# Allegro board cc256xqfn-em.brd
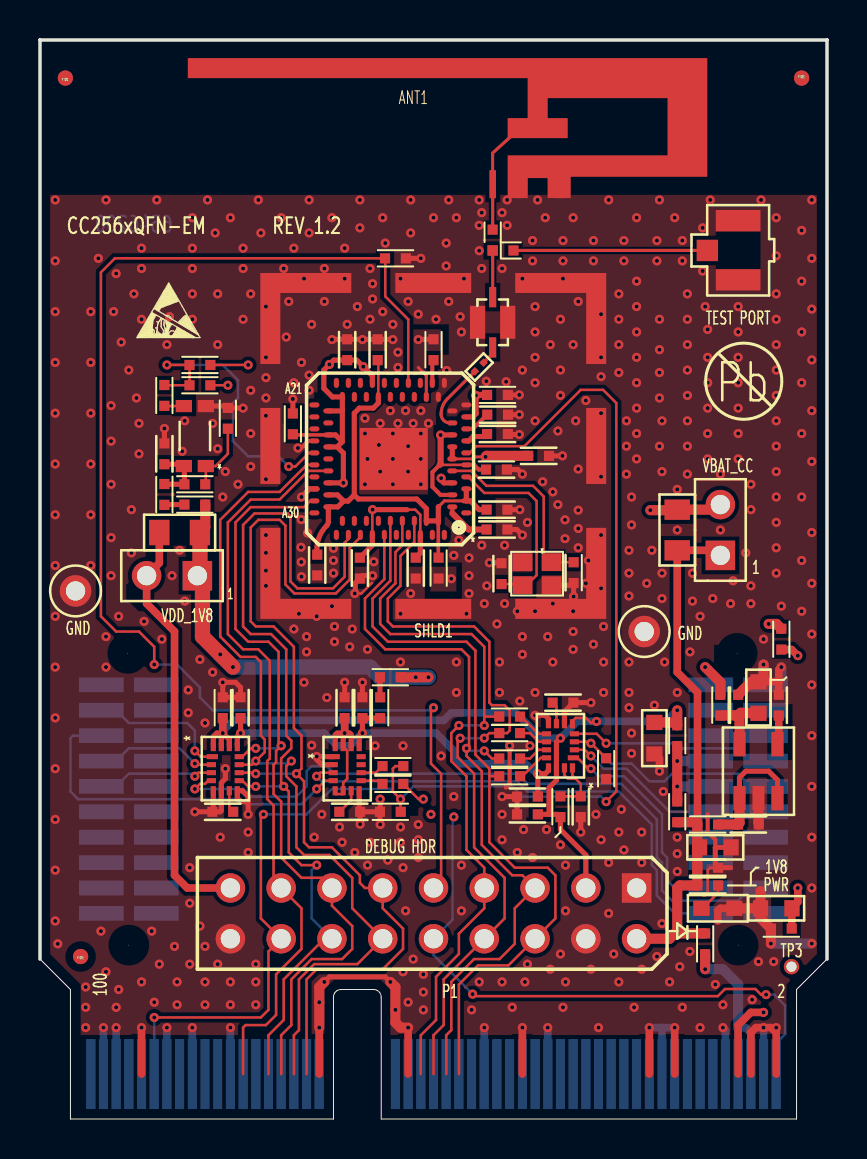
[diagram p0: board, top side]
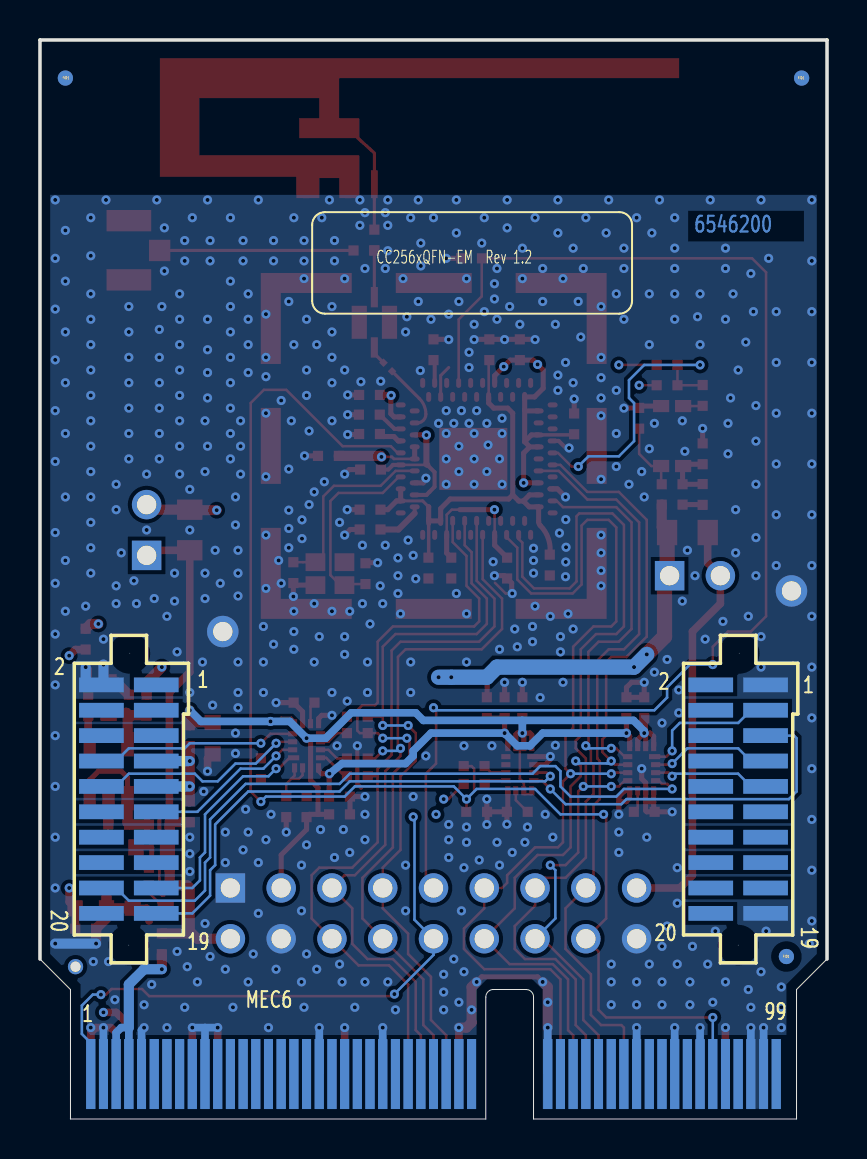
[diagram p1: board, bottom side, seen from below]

Outline 39.37 x 53.98 mm; copper layers: TOP, LYR2_GND, LYR3_PWR, BOTTOM. Coordinates in mm from the lower left corner of the outline.
Outline path: 0,8 0,53.98 39.37,53.98 39.37,8

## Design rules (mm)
nets with their own width: min track width 0.076; nets MLDO_OUT

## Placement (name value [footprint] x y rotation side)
ANT1  N/A  [ANT_IIFA_CC2420_32MIL_MIR]  26.05 46.76 0 top
C1  10uF  [0603]  36.83 10.54 180 top
C2  0.1uF  [0402]  37.08 9.53 180 top
C5  10uF  [0603]  33.78 13.59 0 top
C6  0.1uF  [0402]  33.4 12.57 0 top
C7  1.0uF  [0402]  35.43 14.73 0 top
C8  0.01uF  [0402]  36.96 20.7 90 top
C9  0.1uF  [0402]  34.92 20.7 90 top
C10  10uF  [0603]  35.94 21.08 90 top
C11  0.1uF  [0402]  15.24 20.57 270 top
C12  0.1uF  [0402]  16.13 20.57 90 top
C13  0.1uF  [0402]  9.14 20.57 270 top
C14  0.1uF  [0402]  10.03 20.57 90 top
C15  0.1uF  [0402]  24.38 15.24 0 top
C16  0.1uF  [0402]  24.38 16.13 180 top
C17  0.1uF  [0402]  15.37 38.48 90 top
C18  0.1uF  [0402]  16 27.56 270 top
C19  0.1uF  [0402]  18.8 27.56 270 top
C20  1.0uF  [0402]  22.83 32.49 0 top
C21  1.0uF  [0402]  24.94 33.17 0 top
C22  10pF  [0402]  26.7 27.33 90 top
C23  10pF  [0402]  23.09 27.28 270 top
C24  0.1uF  [0402]  22.86 30.48 0 top
C25  0.47uF  [0402]  16.89 38.48 90 top
C26  0.47uF  [0402]  13.87 27.71 270 top
C27  0.1uF  [0402]  19.68 38.48 90 top
C28  0.1uF  [0402]  22.89 34.26 0 top
C29  0.1uF  [0402]  22.89 35.23 0 top
C30  0.1uF  [0402]  22.86 29.49 0 top
C31  22pF  [0201]  21.97 37.62 45 top
C32  1.0uF  [0402]  22.89 36.22 0 top
C33  0.1uF  [0402]  6.22 33.27 90 top
C34  10uF  [0603]  30.73 19.05 270 top
C35  0.1uF  [0402]  19.94 27.56 270 top
C36  0.1uF  [0402]  12.65 34.77 90 top
D1  GRN  [LED_0603]  33.91 10.54 0 top
FB1  BK1005HS680-T  [FB_0402]  33.4 14.73 0 top
FB2  BK1005HS680-T  [FB_0402]  7.75 30.73 180 top
FB3  BK1005HS680-T  [FB_0402]  17.53 22.1 180 top
FID1  -  [unnamed#2]  38.1 52.07 90 top
FID1#2  -  [unnamed#2]  1.27 52.07 90 top
FID1#3  -  [unnamed#2]  2.03 8.13 90 top
FID1#4  -  [unnamed#2]  38.1 52.07 270 bottom
FID1#5  -  [unnamed#2]  2.03 8.13 270 bottom
FID1#6  -  [unnamed#2]  1.27 52.07 270 bottom
FL1  2.45GHz  [FIL_4_85X53X41]  22.64 39.85 90 top
J1  1x2 THVT  [HDR_THVT_1X2_100_M]  7.87 27.18 270 top
J2  1x2 THVT  [HDR_THVT_1X2_100_M]  34.04 28.19 180 top
LB1  Line 1 Line 2  [LABEL_THT-14]  25.12 40.28 180 bottom
NOREF  -  []  0 0 0 top
NOREF#2  -  []  27.56 19.18 90 top
NOREF#3  -  []  13.08 10.29 90 top
NOREF#4  -  []  24.51 10.29 180 top
NOREF#5  -  []  363.09 -70.36 0 top
NOREF#6  -  []  25.53 9.27 180 top
NOREF#7  -  []  0 0 0 top
NOREF#8  -  []  14.86 6.35 0 top
NOREF#9  -  []  -0.64 0 90 top
NOREF#10  -  []  27.81 76.58 90 top
NOREF#11  -  []  18.54 32.51 180 top
NOREF#12  -  []  0 0 0 top
NOREF#13  -  []  18.54 32.51 180 top
NOREF#14  -  []  16.64 44.2 0 top
NOREF#15  -  []  17.27 32.51 180 top
NOREF#16  -  []  -0.64 0 90 top
NOREF#17  -  []  25.53 32.51 180 top
NOREF#18  -  []  0 0 0 top
NOREF#19  -  []  37.97 6.48 0 top
NOREF#20  -  []  -0.64 0 90 top
NOREF#21  -  []  25.53 9.27 90 top
NOREF#22  -  []  0 0 0 top
NOREF#23  -  []  38.73 54.66 180 bottom
OSC1  32.768KHz 15pF  [OSC_4_SM_134X67X40]  7.75 34.16 90 top
P1  EDGE CARD  [CON_EDGE_50_P635MM]  15.88 0 0 bottom
P2  2x9  [HDR_THVT_2X9_100_M]  29.84 11.56 270 top
P3  COAXIAL  [CON_COAXIAL_UFL-R-SMT]  34.92 43.46 270 top
R1  0  [0402]  31.88 19.18 90 top
R2  0  [0402]  33.27 8.76 270 top
R3  0  [0402]  31.88 15.37 90 top
R4  680  [0402]  33.4 11.68 0 top
R5  0  [0402]  34.04 20.7 90 top
R6  0  [0402]  37.08 24 270 top
R7  0.10  [0805]  6.99 29.34 180 top
R8  0  [0402]  6.22 31.24 90 top
R9  0  [0402]  17.02 20.57 270 top
R10  0.10  [0805]  31.88 29.46 90 top
R11  0  [0402]  28.32 17.53 270 top
R12  10K  [0402]  15.49 15.37 0 top
R13  0  [0402]  17.65 17.65 180 top
R14  0  [0402]  17.65 16.76 180 top
R15  10K  [0402]  9.14 15.37 180 top
R18  0  [0402]  26.04 15.62 270 top
R19  10K  [0402]  27.05 15.62 270 top
R20  10K  [0402]  26.16 20.83 180 top
R21  0  [0402]  23.5 17.14 0 top
R22  0  [0402]  23.5 18.03 0 top
R23  0  [0402]  23.5 19.3 0 top
R24  0  [0402]  23.5 20.13 0 top
R25  0  [0402]  8 36.7 0 top
R26  0  [0402]  6.22 36.2 90 top
R27  10K  [0402]  17.78 43.05 0 top
R28  100K  [0402]  17.53 15.37 180 top
R29  0  [0402]  22.64 43.97 270 top
R30  0  [0402]  23.16 43.45 180 top
R34  10.0K  [0402]  7.75 31.75 0 top
R35  0  [0402]  9.4 35.05 270 top
R36  0  [0402]  8 37.72 180 top
RF1  2x10 SMVT  [CON_SMVT_2X10_50_F_SFM_FLIP_CC]  4.45 16 270 bottom
RF2  2x10 SMVT  [CON_SMVT_2X10_50_F_SFM_FLIP_CC]  34.92 16 270 bottom
SHLD1  xx  [SH_BMI-S-202_650X650]  11.02 25.02 0 top
TP1  Blk  [TP_THVT_060_RND]  1.78 26.42 90 top
TP2  Blk  [TP_THVT_060_RND]  30.23 24.38 90 top
TP3  XX  [TP_VIA_030RND020]  37.59 7.62 90 top
U1  LP2985-18DBV  [SOT23_DBV5]  35.94 17.4 0 top
U2  SN74AVC4T774RSV  [PQFP_RSV16]  15.37 17.53 270 top
U3  SN74AVC4T774RSV  [PQFP_RSV16]  9.27 17.53 270 top
U4  SN74AVC4T774RSV  [PQFP_RSV16]  26.04 18.67 90 top
U5  CC2560RVM  [PVQFN_RVM_EP134X122]  17.53 33.02 90 top
Y1  26MHz  [XTAL_4_SM_83X67X20]  24.87 27.28 180 top

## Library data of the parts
ANT1 = ANT_IIFA_CC2420_32mil_MIR
C1 C5 C10 C34 = CAP_NP
C2 C6-C9 C11-C30 C32 C33 C35 C36 = CAP_NP: alternate symbols: (0402_SMALL)
C31 = CAP_NP: alternate symbols: (0201_small)
D1 = LED_2P
FB1-FB3 = FERRITE_BEAD
FL1 = FILTER_4PIN_GND
J1 J2 = Header_1x2
LB1 = LABEL_BOARD
OSC1 = OSC_4_SM_3-OUT
P1 = CON_EDGE_2x50_25_MEC6
P2 = HEADER_2x9_100_430L
P3 = CON_COAXIAL_UFL-R-SMT
R1-R3 R5-R11 R13 R14 R21-R24 R35 = RESISTOR
R4 R12 R15 R18-R20 R25-R30 R34 R36 = RESISTOR: alternate symbols: (0402_SMALL)
RF1 RF2 = CON_2x10_FLIP_CC
SHLD1 = RF_SHIELD_8P
TP1-TP3 = TESTPOINT
U1 = TPS731xx_DBV5
U2-U4 = SN74AVC4T774_RSV16
U5 = BL6450Q_RVM
Y1 = XTAL_4P_GND

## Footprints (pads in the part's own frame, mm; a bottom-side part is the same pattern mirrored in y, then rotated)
0201
  rect 0.305x0.305 smd: 1(-0.305,0) 2(0.305,0)
0402
  rect 0.508x0.508 smd: 1(-0.521,0) 2(0.521,0)
0603
  rect 0.762x0.813 smd: 1(-0.787,0) 2(0.787,0)
0805
  rect 1.016x1.27 smd: 1(-1.016,0) 2(1.016,0)
ANT_IIFA_CC2420_32MIL_MIR
  rect 0.33x1.397 smd: 1(-3.404,0) 2(-2.108,0) 3(0,0)
CON_COAXIAL_UFL-R-SMT
  rect 1.067x2.235 smd: 1(-1.48,0) 3(1.48,0)
  rect 1.067x1.067 smd: 2(0.01,-1.54)
CON_EDGE_50_P635MM
  rect 0.45x3.5 smd: 1(20.955,-2.25) 2(20.955,-2.25) 3(20.32,-2.25) 4(20.32,-2.25) 5(19.685,-2.25) 6(19.685,-2.25) 7(19.05,-2.25) 8(19.05,-2.25) 9(18.415,-2.25) 10(18.415,-2.25) 11(17.78,-2.25) 12(17.78,-2.25) 13(17.145,-2.25) 14(17.145,-2.25) 15(16.51,-2.25) 16(16.51,-2.25) 17(15.875,-2.25) 18(15.875,-2.25) 19(15.24,-2.25) 20(15.24,-2.25) 21(14.605,-2.25) 22(14.605,-2.25) 23(13.97,-2.25) 24(13.97,-2.25) 25(13.335,-2.25) 26(13.335,-2.25) 27(12.7,-2.25) 28(12.7,-2.25) 29(12.065,-2.25) 30(12.065,-2.25) 31(11.43,-2.25) 32(11.43,-2.25) 33(10.795,-2.25) 34(10.795,-2.25) 35(10.16,-2.25) 36(10.16,-2.25) 37(9.525,-2.25) 38(9.525,-2.25) 39(8.89,-2.25) 40(8.89,-2.25) 41(8.255,-2.25) 42(8.255,-2.25) 43(7.62,-2.25) 44(7.62,-2.25) 45(6.985,-2.25) 46(6.985,-2.25) 47(6.35,-2.25) 48(6.35,-2.25) 49(5.715,-2.25) 50(5.715,-2.25) 51(5.08,-2.25) 52(5.08,-2.25) 53(4.445,-2.25) 54(4.445,-2.25) 55(3.81,-2.25) 56(3.81,-2.25) 57(3.175,-2.25) 58(3.175,-2.25) 59(2.54,-2.25) 60(2.54,-2.25) 61(1.905,-2.25) 62(1.905,-2.25) 63(-1.905,-2.25) 64(-1.905,-2.25) 65(-2.54,-2.25) 66(-2.54,-2.25) 67(-3.175,-2.25) 68(-3.175,-2.25) 69(-3.81,-2.25) 70(-3.81,-2.25) 71(-4.445,-2.25) 72(-4.445,-2.25) 73(-5.08,-2.25) 74(-5.08,-2.25) 75(-5.715,-2.25) 76(-5.715,-2.25) 77(-6.35,-2.25) 78(-6.35,-2.25) 79(-6.985,-2.25) 80(-6.985,-2.25) 81(-7.62,-2.25) 82(-7.62,-2.25) 83(-8.255,-2.25) 84(-8.255,-2.25) 85(-8.89,-2.25) 86(-8.89,-2.25) 87(-9.525,-2.25) 88(-9.525,-2.25) 89(-10.16,-2.25) 90(-10.16,-2.25) 91(-10.795,-2.25) 92(-10.795,-2.25) 93(-11.43,-2.25) 94(-11.43,-2.25) 95(-12.065,-2.25) 96(-12.065,-2.25) 97(-12.7,-2.25) 98(-12.7,-2.25) 99(-13.335,-2.25) 100(-13.335,-2.25)
CON_SMVT_2X10_50_F_SFM_FLIP_CC
  round 0.025 hole 1.346 unplated: (-7.303,0.051) (7.303,0)
  rect 0.737x2.235 smd: 1(-5.715,1.372) 2(-5.715,-1.372) 3(-4.445,1.372) 4(-4.445,-1.372) 5(-3.175,1.372) 6(-3.175,-1.372) 7(-1.905,1.372) 8(-1.905,-1.372) 9(-0.635,1.372) 10(-0.635,-1.372) 11(0.635,1.372) 12(0.635,-1.372) 13(1.905,1.372) 14(1.905,-1.372) 15(3.175,1.372) 16(3.175,-1.372) 17(4.445,1.372) 18(4.445,-1.372) 19(5.715,1.372) 20(5.715,-1.372)
FB_0402
  rect 0.508x0.508 smd: 1(-0.521,0) 2(0.521,0)
FIL_4_85X53X41
  rect 1.651x0.762 smd: 1(0,0.756) 3(0,-0.756)
  rect 1.016x0.356 smd: 2(1.258,0) 4(-1.258,0)
HDR_THVT_1X2_100_M
  rect 1.473x1.473 hole 0.965: 1(0,0)
  round 1.473 hole 0.965: 2(0,-2.54)
HDR_THVT_2X9_100_M
  rect 1.473x1.473 hole 0.965: 1(0,0)
  round 1.473 hole 0.965: 2(2.54,0) 3(0,-2.54) 4(2.54,-2.54) 5(0,-5.08) 6(2.54,-5.08) 7(0,-7.62) 8(2.54,-7.62) 9(0,-10.16) 10(2.54,-10.16) 11(0,-12.7) 12(2.54,-12.7) 13(0,-15.24) 14(2.54,-15.24) 15(0,-17.78) 16(2.54,-17.78) 17(0,-20.32) 18(2.54,-20.32)
LABEL_THT-14
  round 0 smd: 1(0.381,6.731)
LED_0603
  rect 0.813x0.762 smd: 1(-0.826,0) 2(0.826,0)
OSC_4_SM_134X67X40
  rect 0.61x0.813 smd: 1(-1.5,-0.55) 2(1.5,-0.55) 3(1.5,0.55) 4(-1.5,0.55)
PQFP_RSV16
  rect 0.254x0.559 smd: 1(-0.6,-0.648)
  rect 0.254x0.457 smd: 2(-0.2,-0.698) 3(0.2,-0.698) 4(0.6,-0.698) 9(0.6,0.698) 10(0.2,0.698) 11(-0.2,0.698) 12(-0.6,0.698)
  rect 0.457x0.254 smd: 5(1.106,-0.6) 6(1.106,-0.2) 7(1.106,0.2) 8(1.106,0.6) 13(-1.104,0.6) 14(-1.104,0.2) 15(-1.104,-0.2) 16(-1.104,-0.6)
PVQFN_RVM_EP134X122
  oval 0.25x0.5 smd: A1(-2.7,-3.8) A2(-2.1,-3.8) A3(-1.5,-3.8) A4(-0.9,-3.8) A5(-0.3,-3.8) A6(0.3,-3.8) A7(0.9,-3.8) A8(1.5,-3.8) A9(2.1,-3.8) A10(2.7,-3.8) A21(2.7,3.8) A22(2.1,3.8) A23(1.5,3.8) A24(0.9,3.8) A25(0.3,3.8) A26(-0.3,3.8) A27(-0.9,3.8) A28(-1.5,3.8) A29(-2.1,3.8) A30(-2.7,3.8) B1(-2.4,-3.1) B2(-1.8,-3.1) B3(-1.2,-3.1) B4(-0.6,-3.1) B5(0,-3.1) B6(0.6,-3.1) B7(1.2,-3.1) B8(1.8,-3.1) B9(2.4,-3.1) B19(2.4,3.1) B20(1.8,3.1) B21(1.2,3.1) B22(0.6,3.1) B23(0,3.1) B24(-0.6,3.1) B25(-1.2,3.1) B26(-1.8,3.1) B27(-2.4,3.1)
  oval 0.5x0.25 smd: A11(3.8,-2.7) A12(3.8,-2.1) A13(3.8,-1.5) A14(3.8,-0.9) A15(3.8,-0.3) A16(3.8,0.3) A17(3.8,0.9) A18(3.8,1.5) A19(3.8,2.1) A20(3.8,2.7) A31(-3.8,2.7) A32(-3.8,2.1) A33(-3.8,1.5) A34(-3.8,0.9) A35(-3.8,0.3) A36(-3.8,-0.3) A37(-3.8,-0.9) A38(-3.8,-1.5) A39(-3.8,-2.1) A40(-3.8,-2.7) B10(3.1,-2.4) B11(3.1,-1.8) B12(3.1,-1.2) B13(3.1,-0.6) B14(3.1,0) B15(3.1,0.6) B16(3.1,1.2) B17(3.1,1.8) B18(3.1,2.4) B28(-3.1,2.4) B29(-3.1,1.8) B30(-3.1,1.2) B31(-3.1,0.6) B32(-3.1,0) B33(-3.1,-0.6) B34(-3.1,-1.2) B35(-3.1,-1.8) B36(-3.1,-2.4)
  rect 3.099x3.404 smd: EPAD(0,-0.17)
SH_BMI-S-202_650X650
  rect 0.356x0.356 smd: 1(0.5,0.5) 2(8.65,0.5) 3(16.75,0.5) 4(16.8,8.65) 5(16.75,16.75) 6(8.65,16.8) 7(0.5,16.75) 8(0.5,8.65)
SOT23_DBV5
  rect 0.61x1.219 smd: 1(-0.95,-1.35) 2(0,-1.35) 3(0.95,-1.35) 4(0.95,1.35) 5(-0.95,1.35)
TP_THVT_060_RND
  round 1.575 hole 0.965: 1(0,0)
TP_VIA_030RND020
  round 0.762 hole 0.508: 1(0,0)
unnamed#2
  round 0.762 smd: (0,0)
XTAL_4_SM_83X67X20
  rect 0.991x0.889 smd: 1(-0.725,-0.575) 2(0.725,-0.575) 3(0.725,0.575) 4(-0.725,0.575)

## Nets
1V8_IN: C1.1 C2.1 P1.8 R6.2 TP3.1
GND: ANT1.2(G2) ANT1.3(G1) C1.2 C2.2 C5.2 C6.2 C7.2 C8.2 C9.2 C10.2 C11.1 C12.2 C13.1 C14.2 C15.1 C16.2 C17.2 C18.2 C19.2 C20.2 C21.2 C22.1 C23.1 C24.2 C25.2 C26.2 C27.2 C28.2 C29.2 C30.2 C32.2 C33.2 C34.2 C35.2 C36.2 D1.2(CATHODE) FL1.1(GND#1) FL1.3(GND#3) OSC1.2(GND) P1.2 P1.3 P1.6 P1.9 P1.18 P1.19 P1.22 P1.37 P1.42 P1.47 P1.60 P1.63 P1.64 P1.77 P1.83 P1.87 P1.92 P1.95 P1.97 P2.1 P2.4 P2.18 P3.1(GND#1) P3.3(GND#3) R11.2 R12.2 R15.2 R19.2 R20.1 R27.2 R28.2 R35.1 RF1.1 RF1.19 RF2.2 SHLD1.1(G1) SHLD1.2(G2) SHLD1.3(G3) SHLD1.4(G4) SHLD1.5(G5) SHLD1.6(G6) SHLD1.7(G7) SHLD1.8(G8) TP1.1 TP2.1 U1.2(GND) U2.1(A1) U2.2(A2) U2.8(GND) U3.5(DIR3) U3.6(DIR4) U3.8(GND) U4.6(DIR4) U4.8(GND) U5.A10(NC_2) U5.A11(NC_3) U5.A24(VSS_1) U5.A28(VSS_2) U5.B3(VSS_FREF) U5.B9(NC_14) U5.B10(NC_15) U5.B11(VSS_DCO) U5.EPAD(VSS_3) Y1.2(GND#2) Y1.4(GND#4)
VBAT: C5.1 C6.1 FB1.1 J2.1 P2.2 R2.1 R3.1 R4.1 R10.1
VBAT_CC: C21.1 J2.2 R10.2 U5.B5(MLDO_IN) U5.B6(CL1.5_LDO_IN)
VBAT_EDGE: P1.5 P1.7 R2.2
VBAT_MCU: R1.1 R3.2 RF2.7 RF2.9
VDD_1V8: C17.1 C18.1 C19.1 C36.1 J1.2 P2.17 R7.2 U5.A17(VDD_IO_1) U5.A34(VDD_IO_2) U5.A38(VDD_IO_3) U5.B18(VDD_IO_4) U5.B19(VDD_IO_5) U5.B21(VDD_IO_6) U5.B22(VDD_IO_7) U5.B25(VDD_IO_8)
VDD_1V8_32K: C33.1 OSC1.4(VCC) R8.2 R34.1
VDD_1V8_LS: C12.1 C14.1 C16.1 R9.2 U2.13(VCCB) U3.13(VCCB) U4.13(VCCB)
VIN: C7.1 FB1.2 U1.1(IN) U1.3(EN)
ALO: C29.1 U5.A8(ADCPPA_LDO_OUT)
ANT: ANT1.1(FEED) R29.1
AUD_CLK_1V8: P1.52 P2.6 R21.1 U5.B32(AUD_CLK)
AUD_CLK_3V3: RF2.17 U4.1(A1)
AUD_FSYNC_1V8: P1.54 P2.5 R22.1 U5.A35(AUD_FSYNC)
AUD_FSYNC_3V3: RF2.11 U4.2(A2)
AUD_IN_1V8: P1.56 P2.8 R23.1 U5.B34(AUD_IN)
AUD_IN_3V3: R11.1 RF2.10 U4.3(A3)
AUD_OUT_1V8: P1.58 P2.7 R24.1 U5.B33(AUD_OUT)
AUD_OUT_3V3: RF2.8 U4.4(A4)
BT_RF: C31.1 U5.B8(BT_RF)
BT_RF_IN: C31.2 FL1.4(IN)
CLK_REQ_OUT_1V8: P2.9 R27.1 U5.A14(CLK_REQ_OUT)
CLO: C28.1 U5.A7(CL1.5_LDO_OUT)
DCLO: C27.1 U5.A12(DCO_LDO_OUT)
DIG_LDO_OUT: C24.1 C25.1 C26.1 C35.1 U5.A2(DIG_LDO_OUT_1) U5.A3(DIG_LDO_OUT_2) U5.B15(DIG_LDO_OUT_3) U5.B26(DIG_LDO_OUT_4) U5.B27(DIG_LDO_OUT_5) U5.B35(DIG_LDO_OUT_6) U5.B36(DIG_LDO_OUT_7)
HCI_CTS_1V8: P1.70 P2.13 U3.12(B1) U5.A29(HCI_CTS)
HCI_CTS_3V3: RF1.3 U3.1(A1)
HCI_RTS_1V8: P1.72 P2.14 U3.9(B4) U5.A32(HCI_RTS)
HCI_RTS_3V3: RF2.18 U3.4(A4)
HCI_RX_1V8: P1.68 P2.12 U3.11(B2) U5.A26(HCI_RX)
HCI_RX_3V3: RF1.7 U3.2(A2)
HCI_TX_1V8: P1.66 P2.11 U3.10(B3) U5.A33(HCI_TX)
HCI_TX_3V3: RF1.9 U3.3(A3)
MLDO_OUT: C20.1 C32.1 U5.A5(MLDO_OUT_1) U5.A9(MLDO_OUT_2) U5.B2(MLDO_OUT_3) U5.B7(MLDO_OUT_4)
NSHUTDN_3V3: RF2.19 U2.3(A3)
NSHUTDOWN_1V8: P1.89 P2.16 R13.1 R28.1 U5.A6(NSHUTD)
RF_ANT: FL1.2(OUT) R29.2 R30.2
SLO: C30.1 U5.B1(SRAM_LDO_OUT)
SLOW_CLK_EDGE: P1.1 P2.10 R36.1
SLOW_CLK_EXT_1V8: R14.1 R25.2
SLOW_CLK_EXT_3V3: RF1.5 U2.4(A4)
SLOW_CLK_INT_1V8: OSC1.3(OUT) R26.1
TX_DEBUG_1V8: P1.76 P2.15 U5.B24(TX_DBG)
UBAL5: P3.2 R30.1
VIO_HOST: C11.2 C13.2 C15.2 C34.1 P2.3 R1.2 R18.2 U2.5(DIR3) U2.6(DIR4) U2.14(VCCA) U2.15(DIR1) U2.16(DIR2) U3.14(VCCA) U3.15(DIR1) U3.16(DIR2) U4.5(DIR3) U4.14(VCCA)
VOUT: C9.1 C10.1 R5.1 U1.5(OUT)
N29501739: C8.1 U1.4(NR/FB)
N29523209: FB2.1 FB3.1 J1.1 R5.2 R6.1 R7.1
N29523238: FB2.2 R8.1
N29550712: FB3.2 R9.1
N29596482: C22.2 U5.B4(FREFP) Y1.1
N29596500: C23.2 U5.A4(FREFM) Y1.3
N29616633: R20.2 U4.7(O\E\)
N29628438: R12.1 U2.7(O\E\)
N29630665: R15.1 U3.7(O\E\)
N29632228: R18.1 R19.1 U4.15(DIR1) U4.16(DIR2)
N29659196: R25.1 R26.2 R36.2 U5.A25(SLOW_CLK_IN)
N29662683: R13.2 U2.10(B3)
N29662686: R14.2 U2.9(B4)
N29662812: R21.2 U4.12(B1)
N29662815: R22.2 U4.11(B2)
N29662818: R23.2 U4.10(B3)
N29662821: R24.2 U4.9(B4)
N29665006: OSC1.1(EN) R34.2 R35.2
N295651990: D1.1(ANODE) R4.2

Pads without a net: LB1 1; P1 4 10 11 12 13 14 15 16 17 20 21 23 24 25 26 27 28 29 30 31 32 33 34 35 36 38 39 40 41 43 44 45 46 48 49 50 51 53 55 57 59 61 62 65 67 69 71 73 74 75 78 79 80 81 82 84 85 86 88 90 91 93 94 96 98 99 100; RF1 2 4 6 8 10 11 12 13 14 15 16 17 18 20; RF2 1 3 4 5 6 12 13 14 15 16 20; U2 11 12; U5 A1 A13 A15 A16 A18 A19 A20 A21 A22 A23 A27 A30 A31 A36 A37 A39 A40 B12 B13 B14 B16 B17 B20 B23 B28 B29 B30 B31

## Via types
v1: diameter 0.457, hole 0.203, TOP to BOTTOM, 646 vias

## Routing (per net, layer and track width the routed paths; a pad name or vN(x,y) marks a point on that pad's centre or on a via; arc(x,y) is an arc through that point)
1V8_IN: length 7.1
  TOP w0.381: C2.1 37.6,10.53 C1.1 37.62,10.57 37.91,10.86 v1(37.91,11.56) ; v1(36.2,5.33) 35.56,5.33 34.92,4.7 P1.8 ; v1(37.91,23.18) 37.6,23.48 R6.2
GND: length 129.8
  TOP w0.127: 33.15,11.18 33.27,11.18 33.4,11.3 33.4,12.45 33.53,12.57 C6.2 ; v1(15.75,26.29) 16.08,26.29 16.61,26.82
  TOP w0.152: 18.92,37.59 19.33,37.19 U5.B11
  TOP w0.203: U5.A24 13.42,33.92 13.04,33.54 12.93,33.54 v1(12.9,33.57) ; 33.4,15.24 33.4,14.35 33.78,13.97 33.78,13.59 ; v1(23.5,18.67) 23.5,16.76 23.3,16.57
  TOP w0.254: C20.2 23.9,32.49 v1(24.13,32.26) ; v1(13.08,31.11) 13.49,31.52 U5.A28 13.86,31.52 ; 9.07,15.88 9.07,15.42 9.02,15.37 R15.2 ; 9.07,15.88 8.67,15.88 ; 9.07,15.88 U3.6 9.07,16.82 9.27,17.02 v1(9.27,17.53) ; R28.2 17.01,14.74 v1(17.02,14.73) ; R28.2 17.02,15.38 v1(17.02,16) ; R28.2 R12.2 ; C24.2 v1(24,30.48) ; R12.2 v1(16.01,14.74) ; R12.2 15.97,15.45 U2.8 ; C15.1 C16.2 v1(23.11,16.13) ; 8.67,15.88 8.67,15.45 R15.2 ; 8.67,15.88 U3.5 ; U2.1 13.88,18.13 v1(13.84,18.14) 13.84,17.98 14.1,17.73 U2.2 ; Y1.4 26.59,26.7 C22.1 v1(26.7,26.14) ; R15.2 v1(7.75,15.37) ; v1(18.41,33.66) 17.78,33.02 U5.EPAD ; C21.2 v1(26.14,33.17) ; U5.EPAD v1(17.65,33.02) v1(16.95,33.72) ; U5.EPAD 17.02,32.49 v1(17.02,32.38) ; v1(10.16,35.56) R35.1 9.31,35.66 OSC1.2 ; C36.2 v1(12.65,36.02) ; C30.2 23.85,29.49 v1(24.13,29.21) ; U4.8 25.44,20.03 25.27,20.19 v1(24.77,20.19) ; C5.2 33.78,13.59 33.78,12.71 C6.2 34.54,12.57 ; v1(17.65,38.99) 17.51,39 C25.2 16.14,39 v1(16.13,38.99) 16.12,39 C17.2 14.74,39 v1(14.61,38.99) ; C12.2 v1(16.13,21.84) ; v1(22.48,27.83) 23.06,27.83 C23.1 ; C32.2 v1(23.98,36.22) ; 10.41,15.88 10.41,16.13 10.12,16.42 U3.8 9.87,16.04 10.03,15.88 10.41,15.88 ; 10.41,15.88 v1(10.41,15.24) ; R19.2 v1(27.05,14.35) ; 23.38,34.24 v1(23.98,34.24) ; v1(18.92,38.99) 19.06,39 C27.2 ; U4.6 26.23,20.38 R20.1 v1(27.56,20.83) ; v1(15.24,21.84) C11.1 ; v1(16.64,27.18) 16.14,27.18 C18.2 15.77,26.81 15.77,26.31 v1(15.75,26.29) ; C29.2 v1(23.98,35.23) ; v1(20.07,32.05) 20.07,31.95 20.2,31.82 U5.B3 ; R27.2 v1(19.05,43.05) ; v1(17.53,6.86) 17.27,7.11 14.48,7.11 v1(14.22,6.86) ; C33.2 v1(6.22,34.54) ; C13.1 v1(9.14,21.84) 9.78,21.84 10.03,21.59 C14.2 C13.1
  TOP w0.381: 33.91,9.91 33.91,10.41 34.04,10.54 D1.2 ; P1.60 v1(18.41,4.57) ; v1(37.08,22.61) 36.96,22.48 36.96,21.84 ; P1.42 v1(24.13,4.57) ; 36.83,4.32 36.58,4.57 v1(36.2,4.57) 35.81,4.57 35.56,4.32 P1.6 ; 36.83,4.32 v1(36.83,4.57) ; 36.83,4.32 P1.2 ; P1.22 v1(30.48,4.57) ; 36.96,21.84 36.93,21.87 35.97,21.87 ; 36.96,21.84 C8.2 ; v1(30.99,17.4) 30.99,18.03 30.76,18.26 C34.2 ; P1.18 v1(31.75,4.57) ; P1.63 v1(13.97,4.57) ; P1.92 v1(5.08,4.57)
  TOP w0.508: v1(36.56,8.78) C2.2 36.04,10.05 C1.2 ; v1(14.22,6.86) 13.97,6.6 v1(13.97,5.84) v1(13.97,4.57) ; v1(17.53,6.86) 17.78,6.6 v1(17.78,5.46) 17.78,4.83 18.03,4.57 v1(18.41,4.57) ; D1.2 C1.2 ; C1.2 36.04,11.4 ; C7.2 35.94,14.87 U1.2 ; v1(36.2,22.73) 36.2,22.1 35.97,21.87 C10.2 35.57,21.87 C9.2
  BOTTOM w0.381: v1(36.2,4.57) P1.3 ; P1.63 v1(13.97,4.57) ; P1.95 v1(3.81,4.57) ; v1(34.16,4.57) 34.29,4.45 P1.9 ; P1.77 v1(9.53,4.57) ; v1(31.75,4.57) 31.11,4.57 ; 31.11,4.57 P1.19 ; 31.11,4.57 v1(30.48,4.57) ; P1.97 v1(3.17,4.57) ; P1.47 v1(22.23,4.57) ; P1.83 v1(7.62,4.57) ; P1.87 v1(6.35,4.57) ; P1.37 v1(25.4,4.57)
  BOTTOM w0.508: v1(36.2,22.73) 36.2,21.82 RF2.2 36.83,21.72 37.08,21.97 v1(37.08,22.61) ; v1(36.56,8.78) v1(38.61,8.78)
  vias: v1(0.76,45.97) v1(0.76,42.93) v1(0.76,40.39) v1(0.76,37.85) v1(0.76,35.31) v1(0.76,32.77) v1(0.76,30.23) v1(0.76,27.69) v1(0.76,25.15) v1(0.76,22.61) v1(0.76,20.07) v1(0.76,17.53) v1(0.76,14.99) v1(0.76,12.45) v1(0.76,9.91) v1(0.89,8.76) v1(2.29,6.6) v1(2.29,5.59) v1(2.29,4.57) v1(2.54,40.39) v1(2.54,37.85) v1(2.54,35.31) v1(2.54,32.77) v1(2.54,30.23) v1(2.54,27.69) v1(2.92,43.05) v1(3.05,9.4) v1(3.3,45.97) v1(3.3,24.13) v1(3.3,22.61) v1(3.3,7.37) v1(3.56,35.69) v1(3.56,33.91) v1(3.56,31.75) v1(3.56,29.08) v1(3.56,27.18) v1(3.68,40.39) v1(3.81,42.29) v1(3.81,5.59) v1(3.94,25.15) v1(3.94,6.48) v1(4.06,38.86) v1(4.45,37.47) v1(4.57,30.48) v1(4.57,28.32) v1(4.7,41.27) v1(4.83,36.07) v1(4.95,34.8) v1(4.95,33.27) v1(5.08,43.56) v1(5.08,42.55) v1(5.08,40.01) v1(5.08,6.86) v1(5.21,24.89) v1(5.59,9.4) v1(5.71,5.84) v1(5.84,45.97) v1(5.97,7.75) v1(6.1,24) v1(6.35,41.27) v1(6.35,38.73) v1(6.48,40.13) v1(6.6,27.18) v1(6.73,8.64) v1(6.86,6.86) v1(6.86,5.71) v1(6.99,28.45) v1(7.11,33.4) v1(7.24,34.92) v1(7.24,25.91) v1(7.42,21.46) v1(7.42,20.32) v1(7.49,12.57) v1(7.49,10.79) v1(7.49,7.75) v1(7.62,45.09) v1(7.62,43.56) v1(7.62,42.55) v1(7.62,41.27) v1(7.62,40.01) v1(8,22.99) v1(8,9.65) v1(8.26,19.81) v1(8.26,8.64) v1(8.26,6.86) v1(8.26,5.71) v1(8.38,45.97) v1(8.64,34.8) v1(8.64,22.35) v1(8.76,44.32) v1(8.89,41.27) v1(8.89,38.73) v1(8.89,33.53) v1(8.89,7.75) v1(9.02,14.1) v1(9.14,31.11) v1(9.27,32.38) v1(9.53,45.09) v1(9.53,6.86) v1(9.53,5.71) v1(9.91,31.75) v1(10.16,43.56) v1(10.16,42.55) v1(10.16,40.01) v1(10.41,14.35) v1(10.41,13.34) v1(10.54,41.27) v1(10.54,36.45) v1(10.54,34.29) v1(10.54,32.64) v1(10.79,7.75) v1(10.79,6.86) v1(10.79,5.71) v1(10.92,45.97) v1(11.05,44.32) v1(11.3,40.64) v1(11.3,38.1) v1(11.3,37.08) v1(11.3,36.07) v1(11.3,35.18) v1(11.3,32) v1(11.3,29.21) v1(11.3,28.32) v1(11.3,27.43) v1(11.3,26.67) v1(12.06,45.09) v1(12.19,42.55) v1(12.32,39.12) v1(12.45,40.89) v1(12.7,43.56) v1(12.7,36.83) v1(12.7,24.51) v1(12.95,25.27) v1(13.08,37.85) v1(13.07,29.98) v1(13.06,28.6) v1(13.07,27.86) v1(13.08,27.13) v1(13.21,42.04) v1(13.21,21.84) v1(13.34,24.13) v1(13.34,23.37) v1(13.39,29.31) v1(13.46,45.97) v1(13.46,44.32) v1(13.46,37.21) v1(13.46,36.45) v1(13.59,39.75) v1(13.59,18.69) v1(13.72,14.1) v1(13.84,25.15) v1(14.1,15.24) v1(14.22,42.55) v1(14.22,40.89) v1(14.35,21.08) v1(14.61,45.09) v1(14.61,25.65) v1(14.68,28.55) v1(14.68,27.94) v1(14.68,27.3) v1(14.73,24.64) v1(14.73,23.88) v1(14.99,14.61) v1(15.11,13.84) v1(15.24,43.56) v1(15.24,42.04) v1(15.37,39.75) v1(15.49,23.62) v1(15.62,24.51) v1(15.75,13.34) v1(15.88,40.64) v1(16,45.97) v1(16,44.58) v1(16.26,35.05) v1(16.26,34.29) v1(16.26,31.75) v1(16.38,33.02) v1(16.38,23.5) v1(16.38,12.7) v1(16.51,42.55) v1(16.51,40.01) v1(16.51,13.84) v1(16.64,41.78) v1(16.64,41.02) v1(16.7,27.88) v1(16.76,18.67) v1(17.02,34.8) v1(17.14,45.09) v1(17.14,40.39) v1(17.27,43.81) v1(17.4,12.95) v1(17.53,35.43) v1(17.65,39.75) v1(17.65,34.29) v1(17.65,31.75) v1(17.91,38.35) v1(17.91,37.59) v1(17.91,34.8) v1(18.03,42.04) v1(18.03,25.27) v1(18.03,22.86) v1(18.03,14.61) v1(18.03,13.84) v1(18.16,18.67) v1(18.16,12.57) v1(18.16,7.37) v1(18.29,35.43) v1(18.29,10.41) v1(18.41,40.89) v1(18.41,32.38) v1(18.41,5.84) v1(18.54,45.97) v1(18.54,44.32) v1(18.54,26.29) v1(18.67,34.8) v1(18.67,8) v1(18.92,40.26) v1(18.92,14.73) v1(18.92,13.97) v1(18.92,13.08) v1(19.05,35.43) v1(19.05,34.29) v1(19.05,33.02) v1(19.05,31.75) v1(19.18,7.24) v1(19.18,6.35) v1(19.18,5.46) v1(19.43,34.8) v1(19.68,45.09) v1(19.81,40.01) v1(20.07,18.16) v1(20.32,43.81) v1(20.32,42.67) v1(20.35,37.44) v1(20.45,45.97) v1(20.45,40.89) v1(20.57,27.03) v1(20.7,28.19) v1(20.7,16.13) v1(20.83,45.09) v1(20.83,22.86) v1(20.83,21.34) v1(21.02,40.13) v1(20.95,28.96) v1(21.08,39.37) v1(21.08,12.7) v1(21.08,10.41) v1(21.21,42.04) v1(21.34,25.27) v1(21.46,28.07) v1(21.46,27.18) v1(21.46,26.29) v1(21.59,5.46) v1(21.97,45.97) v1(21.97,44.7) v1(21.97,43.43) v1(21.97,6.86) v1(22.1,45.34) v1(22.1,42.55) v1(22.1,28.7) v1(22.23,25.78) v1(22.33,36.91) v1(22.35,26.67) v1(22.86,24.77) v1(22.99,22.86) v1(22.99,21.34) v1(23.11,45.34) v1(23.11,42.55) v1(23.11,15.24) v1(23.11,13.97) v1(23.11,6.86) v1(23.24,28.7) v1(23.24,25.78) v1(23.32,36.88) v1(23.37,45.97) v1(23.37,44.7) v1(23.62,5.59) v1(23.88,25.4) v1(23.88,13.34) v1(24,20.9) v1(24.13,42.04) v1(24.13,37.47) v1(24.13,24.13) v1(24.13,23.24) v1(24.19,14.48) v1(24.26,6.86) v1(24.38,29.84) v1(24.38,7.75) v1(24.51,18.67) v1(24.64,43.94) v1(24.64,42.93) v1(24.64,13.08) v1(24.77,40.64) v1(24.77,39.37) v1(24.77,38.1) v1(24.77,36.83) v1(24.77,34.92) v1(24.77,25.4) v1(24.77,21.34) v1(24.89,45.97) v1(25.15,31.88) v1(25.27,45.09) v1(25.34,14.48) v1(25.4,24.13) v1(25.53,38.73) v1(25.53,7.49) v1(25.65,31.37) v1(25.65,25.78) v1(25.65,22.86) v1(25.91,34.42) v1(25.91,30.73) v1(26.04,40.01) v1(26.04,37.47) v1(26.04,36.2) v1(26.04,13.72) v1(26.04,8.26) v1(26.16,43.94) v1(26.16,42.93) v1(26.16,42.04) v1(26.16,5.59) v1(26.26,29.97) v1(26.26,29.03) v1(26.29,12.7) v1(26.29,10.41) v1(26.29,6.86) v1(26.67,45.09) v1(26.67,38.73) v1(26.67,25.4) v1(26.67,24.38) v1(26.67,23.5) v1(26.8,34.92) v1(26.92,40.89) v1(26.92,32.51) v1(26.92,30.45) v1(26.92,29.54) v1(26.92,28.57) v1(27.3,35.94) v1(27.3,26.8) v1(27.43,27.94) v1(27.56,7.49) v1(27.69,43.94) v1(27.69,42.93) v1(27.69,23.75) v1(27.81,15.24) v1(27.94,4.57) v1(28.07,40.26) v1(28.07,38.1) v1(28.07,37.13) v1(28.07,35.31) v1(28.07,32.13) v1(28.07,29.21) v1(28.07,26.54) v1(28.07,13.97) v1(28.19,24.64) v1(28.19,22.86) v1(28.19,21.34) v1(28.45,45.97) v1(28.45,12.83) v1(28.45,10.29) v1(28.7,8.26) v1(28.96,41.27) v1(28.96,40.01) v1(28.96,38.73) v1(28.96,37.34) v1(28.96,14.35) v1(28.96,6.86) v1(29.08,15.49) v1(29.21,43.94) v1(29.21,42.93) v1(29.21,13.46) v1(29.34,34.92) v1(29.34,33.66) v1(29.34,32.26) v1(29.46,28.45) v1(29.46,27.3) v1(29.46,26.16) v1(29.46,22.86) v1(29.46,21.34) v1(29.46,20.57) v1(29.59,31.11) v1(29.59,29.72) v1(29.59,19.3) v1(29.59,18.29) v1(29.72,5.59) v1(29.84,45.09) v1(29.84,41.91) v1(29.84,40.64) v1(29.84,39.37) v1(29.84,38.1) v1(29.84,36.83) v1(29.84,35.56) v1(29.84,34.29) v1(29.84,33.02) v1(30.1,14.35) v1(30.1,12.83) v1(30.1,7.49) v1(30.35,26.8) v1(30.61,28.45) v1(30.73,20.7) v1(30.86,43.94) v1(30.86,42.93) v1(30.86,8.13) v1(30.99,45.97) v1(30.99,40.01) v1(30.99,38.48) v1(30.99,37.34) v1(30.99,36.07) v1(30.99,33.66) v1(31.11,34.92) v1(31.11,32.38) v1(31.11,27.3) v1(31.11,26.04) v1(31.11,9.78) v1(31.24,22.86) v1(31.18,16.38) v1(31.5,6.86) v1(31.75,45.09) v1(31.88,31.5) v1(31.88,29.46) v1(31.88,21.34) v1(31.88,14.1) v1(31.88,13.27) v1(31.88,12.38) v1(32,7.62) v1(32.13,43.94) v1(32.13,42.93) v1(32.13,5.59) v1(32.38,41.27) v1(32.38,40.01) v1(32.38,38.73) v1(32.38,37.47) v1(32.38,36.2) v1(32.38,34.92) v1(32.38,33.66) v1(32.38,32.26) v1(32.51,23.37) v1(32.51,8.38) v1(32.64,27.3) v1(32.64,25.91) v1(33.02,25.15) v1(33.02,4.57) v1(33.15,44.58) v1(33.15,42.42) v1(33.27,40.64) v1(33.4,39.5) v1(33.4,38.1) v1(33.4,36.83) v1(33.4,35.56) v1(33.4,34.29) v1(33.4,33.02) v1(33.53,45.97) v1(33.66,26.04) v1(33.78,6.73) v1(34.04,32.26) v1(34.04,29.46) v1(34.16,5.71) v1(34.54,25.78) v1(34.67,26.92) v1(34.92,40.64) v1(34.92,39.37) v1(34.92,38.1) v1(34.92,36.83) v1(34.92,35.56) v1(34.92,34.29) v1(34.92,33.02) v1(35.31,28.32) v1(35.56,31.75) v1(35.56,30.48) v1(35.56,26.67) v1(35.56,25.78) v1(35.62,5.97) v1(35.94,7.87) v1(36.07,45.97) v1(36.2,24) v1(36.7,7.87) v1(36.83,45.09) v1(36.83,43.18) v1(36.83,41.27) v1(36.83,40.01) v1(36.83,38.73) v1(36.83,37.47) v1(36.83,36.2) v1(36.83,34.92) v1(36.83,33.66) v1(36.83,32.38) v1(36.83,31.11) v1(36.83,29.84) v1(36.83,28.57) v1(36.83,27.3) v1(37.08,25.65) v1(38.1,44.45) v1(38.1,41.91) v1(38.1,39.37) v1(38.1,36.83) v1(38.1,34.29) v1(38.1,31.11) v1(38.1,27.94) v1(38.1,25.4) v1(38.61,45.97) v1(38.61,43.05) v1(38.61,40.51) v1(38.61,37.97) v1(38.61,35.43) v1(38.61,32.89) v1(38.61,29.34) v1(38.61,26.8) v1(38.61,24.26) v1(38.61,21.72) v1(38.61,19.18) v1(38.61,16.64) v1(38.61,14.1) v1(38.61,11.56)
VBAT: length 27.6
  TOP w0.381: J2.1 33.78,28.45 R10.1 31.88,22.35 32.89,21.34 32.89,14.74 FB1.1
  TOP w0.508: R2.1 31.99,9.28 31.88,9.4 ; 31.88,9.4 31.88,11.56 32,11.68 R4.1 C6.1 32.88,13.6 C5.1 32.88,13.83 FB1.1 32.87,14.85 R3.1 ; 31.88,9.4 31.5,9.02 P2.2
VBAT_CC: length 17.4
  TOP w0.14: U5.B5 21.67,33.02 21.77,33.12 v1(22.29,33.12)
  TOP w0.254: U5.B5 U5.B6
  TOP w0.508: C21.1 22.34,33.17 v1(22.29,33.12) ; J2.2 33.78,30.48 R10.2 31.85,30.45 v1(30.53,30.45)
  LYR3_PWR w0.508: v1(30.53,30.45) 27.86,30.45 25.2,33.12 v1(22.29,33.12)
VBAT_EDGE: length 10
  TOP w0.508: R2.2 v1(33.27,7.49)
  BOTTOM w0.381: P1.5 35.56,4.32 35.31,4.57 34.92,4.57 P1.7
  BOTTOM w0.508: v1(33.27,7.49) 34.16,7.49 34.92,6.73 34.92,4.57
VBAT_MCU: length 6.1
  TOP w0.508: R1.1 v1(31.88,17.91) v1(31.88,16.64) R3.2
  BOTTOM w0.508: RF2.9 v1(31.88,16.64) ; RF2.7 v1(31.88,17.91)
VDD_1V8: length 42.9
  TOP w0.127: U5.A34 16.63,30.47 v1(16.64,30.48) ; 18.36,30.48 18.77,30.48 19.03,30.22 U5.A38
  TOP w0.152: 12.68,34.22 C36.1
  TOP w0.178: U5.B21 12.68,34.22
  TOP w0.254: 14.87,33.62 U5.B22 ; 14.87,33.62 15.18,33.31 v1(15.18,31.82) U5.B25 ; 14.87,33.62 15.13,33.88 ; U5.B21 14.78,34.22 15.13,33.88 ; 18.36,30.48 v1(16.64,30.48) ; 15.13,35.45 U5.B18 14.63,36.12 14.2,36.55 14.2,37.47 v1(14.48,37.74) 14.69,37.96 C17.1 15.85,37.96 v1(16.17,37.64) 16.63,37.18 U5.A17 ; 15.13,35.45 15.13,33.88 ; 15.13,35.45 15.1,35.42 U5.B19 ; C19.1 19.03,28.31 U5.A38 ; U5.A34 16.63,28.7 C18.1
  TOP w0.381: R7.2 5.97,27.81 J1.2 5.33,25.78 6.73,24.38 6.73,12.19 7.37,11.56 P2.17 ; 16.64,30.48 v1(16.64,30.48)
VDD_1V8_32K: length 2.9
  TOP w0.254: C33.1 7.11,32.75 OSC1.4 7.23,32.63 R34.1 6.24,31.75 R8.2
VDD_1V8_LS: length 22.1
  TOP w0.254: U4.13 25.44,17.43 25.27,17.27 v1(24.89,17.27) 24.9,17.13 C16.1 ; U2.13 15.97,19.14 v1(16.13,19.3) C12.1 R9.2 ; U3.13 9.87,19.14 v1(10.03,19.3) C14.1
  BOTTOM w0.381: v1(24.89,17.27) 24.26,17.78 21.08,17.78 20.7,18.16 20.7,18.41 19.81,19.3 v1(16.13,19.3) 15.49,18.67 14.86,18.67 14.22,19.3 v1(10.03,19.3)
VIN: length 6.5
  TOP w0.254: U1.3 36.89,16.96 36.45,17.4 35.31,17.4 34.99,17.08 U1.1
  TOP w0.508: FB1.2 C7.1 34.99,14.81 U1.1
ALO: length 1.3
  TOP w0.203: C29.1 21.63,34.52 U5.A8
ANT: length 2.3
  TOP w0.157: 22.64,46.76 R29.1
AUD_CLK_1V8: length 38.5
  TOP w0.127: P1.52 20.95,6.73 21.91,7.68 23.43,7.68 P2.6 25.78,10.03 25.78,12.19 25.4,12.57 23.75,12.57 22.48,13.84 22.48,17.14 ; U5.B32 17.53,26.92 16.64,26.04 16.64,24.64 17.4,23.88 21.34,23.88 21.78,23.43 21.78,18.22 22.48,17.53 22.48,17.14 ; 22.48,17.14 R21.1
AUD_CLK_3V3: length 11.4
  TOP w0.127: U4.1 26.89,18.07 27.43,17.53 v1(27.56,17.53)
  BOTTOM w0.127: RF2.17 31.75,11.56 31.37,11.94 31.37,13.08 31.11,13.34 31.11,15.24 29.21,17.14 27.94,17.14 v1(27.56,17.53)
AUD_FSYNC_1V8: length 38
  TOP w0.127: R22.1 22.61,18.03 v1(22.23,18.41) ; U5.A35 17.23,27.01 16.26,26.04 16.26,24.51 17.27,23.5 21.08,23.5 21.46,23.11 21.46,18.67 v1(21.34,18.54) 21.34,18.16 22.1,17.4 22.1,13.72 23.62,12.19 24.13,12.19 P2.5 23.75,10.54 23.75,8.76 22.99,8 21.72,8 20.57,6.86 20.57,4.45 20.32,4.19 P1.54
  BOTTOM w0.127: v1(22.23,18.41) 21.34,18.41 v1(21.34,18.54)
AUD_FSYNC_3V3: length 8.1
  TOP w0.127: v1(27.56,18.16) 27.25,18.47 U4.2
  BOTTOM w0.127: v1(27.56,18.16) 28.19,17.53 29.34,17.53 31.5,15.37 RF2.11
AUD_IN_1V8: length 38.2
  TOP w0.127: v1(21.02,19.05) 20.89,18.92 20.89,18.1 21.72,17.27 21.72,13.59 23.24,12.06 23.24,10.03 P2.8 20.19,6.99 20.19,4.7 19.68,4.19 P1.56 ; v1(22.23,19.05) 22.48,19.3 R23.1 23.37,19.3 23.5,19.43 23.5,20.45 23.24,20.7 22.61,20.7 22.48,20.83 22.48,23.88 21.72,24.64 17.65,24.64 17.4,24.89 17.4,26.04 18.03,26.67 18.03,28.17 18.73,28.86 U5.B34
  BOTTOM w0.127: v1(22.23,19.05) v1(21.02,19.05)
AUD_IN_3V3: length 11.9
  TOP w0.127: U4.3 27.49,18.87 v1(27.56,18.8) 27.57,18.8 R11.1
  BOTTOM w0.127: v1(27.56,18.8) 28.57,17.78 29.59,17.78 30.48,16.89 31.24,16.89 31.62,17.27 34.92,17.27 35.56,16.64 RF2.10
AUD_OUT_1V8: length 36.9
  TOP w0.127: 22.23,20.19 22.29,20.13 R24.1 ; 22.23,20.19 22.23,23.62 21.59,24.26 17.53,24.26 17.02,24.77 17.02,26.04 17.78,26.8 17.78,28.36 18.13,28.7 U5.B33 ; 22.23,20.19 v1(22.23,19.68) ; P1.58 19.05,4.19 19.81,4.95 19.81,7.11 20.95,8.26 20.95,9.27 22.23,10.54 P2.7 22.23,12.57 21.34,13.46 21.34,17.14 20.57,17.91 20.57,19.3 v1(20.95,19.68)
  BOTTOM w0.127: v1(20.95,19.68) v1(22.23,19.68)
AUD_OUT_3V3: length 10.1
  TOP w0.127: v1(28.32,18.8) 27.85,19.27 U4.4
  BOTTOM w0.127: v1(28.32,18.8) 31.88,18.8 32.13,18.54 34.92,18.54 35.56,17.91 RF2.8
BT_RF: length 3.6
  TOP w0.157: U5.B8 20.5,34.82 arc(20.19,34.95) 20.07,35.26 arc(20.15,35.68) 20.39,36.04 C31.1
BT_RF_IN: length 1
  TOP w0.157: FL1.4 22.64,38.29 C31.2
CLK_REQ_OUT_1V8: length 67.3
  TOP w0.127: U5.A14 18.43,39.99 17.27,41.15 17.27,43.04 R27.1 3.75,43.05 3.05,42.35 3.05,25.15 3.81,24.38 4.95,24.38 5.71,23.62 v1(5.71,22.73) ; P2.9 20.07,11.94 20.07,17.27 19.56,17.78 19.56,20.45 v1(19.68,20.57)
  BOTTOM w0.127: v1(19.68,20.57) 19.56,20.45 8.64,20.45 8,21.08 8,21.59 6.86,22.73 v1(5.71,22.73)
CLO: length 1.2
  TOP w0.254: U5.A7 21.45,33.92 21.67,34.14 22.21,34.14 C28.1
DCLO: length 1.2
  TOP w0.203: U5.A12 19.63,37.9 C27.1
DIG_LDO_OUT: length 23.6
  TOP w0.127: C25.1 16.93,37.93 U5.B15
  TOP w0.152: 19.94,30.63 20.23,30.92 U5.A2
  TOP w0.178: C35.1 19.93,28.09 U5.B36
  TOP w0.254: U5.A3 U5.A2 21.53,30.92 21.97,30.48 C24.1 ; 15.72,31.22 15.93,31.01 18.85,31.01 19.33,30.53 U5.B35 U5.B36 19.93,30.62 19.94,30.63 ; 15.72,31.22 15.72,35.31 15.98,35.56 16.67,35.56 16.93,35.81 U5.B15 ; 15.72,31.22 15.42,30.91 15.19,30.91 ; 15.19,30.91 14.88,31.22 U5.B26 ; 15.19,30.91 14.9,30.62 U5.B27 14.43,29.88 arc(14.4,29.78) 14.34,29.68 arc(13.93,29.02) C26.1
HCI_CTS_1V8: length 40.7
  TOP w0.127: 13.86,30.92 U5.A29 13.52,30.92 13.21,30.61 10.54,30.61 9.78,29.84 9.78,24.51 10.41,23.88 11.43,23.88 11.94,23.37 11.94,18.8 v1(12.06,18.67) 11.81,18.41 11.81,17.84 11.68,17.72 11.68,16.26 12.06,15.88 12.06,13.08 13.08,12.06 14.1,12.06 P2.13 14.61,10.67 15.62,9.65 15.62,8.51 15.11,8 13.59,8 12.57,6.99 12.57,4.7 12.06,4.19 P1.70 ; v1(10.79,18.54) 10.54,18.54 10.12,18.13 U3.12
  BOTTOM w0.127: v1(12.06,18.67) 11.94,18.54 v1(10.79,18.54)
HCI_CTS_3V3: length 7.1
  TOP w0.127: v1(7.75,18.41) 8.04,18.13 U3.1
  BOTTOM w0.127: v1(7.75,18.41) 7.75,19.43 7.37,19.81 4.45,19.81 3.81,20.45 RF1.3
HCI_RTS_1V8: length 46.1
  TOP w0.127: U5.A32 15.43,29.01 15.24,28.83 15.24,27.13 14.66,26.54 12.88,26.54 12.53,26.89 12.53,30.15 12.39,30.29 10.73,30.29 10.16,29.72 10.16,24.64 10.54,24.26 11.56,24.26 12.32,23.5 12.32,19.18 12.57,18.92 12.57,18.54 12.06,18.03 12.06,16.76 v1(12.19,16.64) 12.45,16.38 12.45,13.34 13.08,12.7 v1(13.84,12.7) ; P1.72 11.43,4.19 12.19,4.95 12.19,6.99 14.22,9.02 P2.14 ; U3.9 10.12,16.93 10.41,16.64 v1(10.79,16.64)
  BOTTOM w0.127: P2.14 13.59,10.03 13.59,12.45 v1(13.84,12.7) ; v1(12.19,16.64) v1(10.79,16.64)
HCI_RTS_3V3: length 35.8
  TOP w0.127: U3.4 8.42,16.93 8.26,16.76 8,16.76 v1(7.75,16.51)
  BOTTOM w0.127: v1(7.75,16.51) 10.16,16.51 10.54,16.13 12.83,16.13 13.34,16.64 13.34,17.4 13.59,17.65 14.35,17.65 14.73,17.27 23.88,17.27 24.38,16.76 29.08,16.76 30.86,14.99 30.86,13.08 31.11,12.83 31.11,11.43 31.62,10.92 34.92,10.92 35.56,11.56 RF2.18
HCI_RX_1V8: length 44
  TOP w0.127: U3.11 10.61,17.73 v1(10.79,17.91) 11.24,18.35 11.24,18.99 11.05,19.18 11.05,22.86 10.79,23.11 10.03,23.11 9.02,24.13 9.02,29.97 10.41,31.37 11.99,31.37 13.34,32.72 U5.A26 13.86,32.72 ; v1(12.57,17.91) 12.32,17.65 12.32,17.14 12.83,16.64 12.83,13.59 13.21,13.21 14.48,13.21 15.62,12.06 15.62,10.54 P2.12 15.88,7.75 13.72,7.75 12.95,6.99 12.95,4.45 12.7,4.19 P1.68
  BOTTOM w0.127: v1(10.79,17.91) 10.92,17.78 11.05,17.79 12.46,17.79 v1(12.57,17.91)
HCI_RX_3V3: length 6.1
  TOP w0.127: v1(7.75,17.78) 7.8,17.73 U3.2
  BOTTOM w0.127: v1(7.75,17.78) 6.99,18.54 4.45,18.54 3.81,17.91 RF1.7
HCI_TX_1V8: length 50.3
  TOP w0.127: U5.A33 16.03,29.11 15.49,28.57 15.49,26.99 14.8,26.29 12.73,26.29 12.28,26.74 12.28,29.68 11.99,29.97 10.92,29.97 10.54,29.59 10.54,24.89 10.79,24.64 11.68,24.64 12.7,23.62 12.7,19.56 13.08,19.18 13.08,17.53 v1(12.83,17.27) 13.21,16.89 13.21,13.84 13.46,13.59 14.61,13.59 16,12.19 16,11.81 16.26,11.56 P2.11 17.14,10.54 18.16,9.53 18.16,8.51 17.14,7.49 13.84,7.49 13.34,6.99 P1.66 ; v1(10.79,17.27) 10.74,17.33 U3.10
  BOTTOM w0.127: v1(12.83,17.27) v1(10.79,17.27)
HCI_TX_3V3: length 5.9
  TOP w0.127: v1(7.75,17.14) 7.93,17.33 U3.3
  BOTTOM w0.127: v1(7.75,17.14) 7.62,17.27 4.45,17.27 3.81,16.64 RF1.9
MLDO_OUT: length 12.4
  TOP w0.127: 19.99,32.72 U5.A5 ; 19.89,31.37 19.89,31.37
  TOP w0.203: 19.89,31.37 20.03,31.22 U5.B2 ; 19.99,32.72 19.63,32.36 19.63,31.63 19.89,31.37 ; U5.A5 21.71,32.72 21.95,32.49 C20.1
  TOP w0.254: U5.A9 21.66,35.12 21.82,35.28 21.82,36.07 21.81,36.08 v1(21.81,36.2) 21.71,36.2 ; U5.B7 20.05,34.22 v1(20.04,34.21)
  TOP w0.305: C32.1 21.83,36.22 v1(21.81,36.2) ; v1(20.04,34.21) 20.04,32.77 19.99,32.72
  LYR3_PWR w0.381: v1(21.81,36.2) 21.81,34.99 21.03,34.21 v1(20.04,34.21)
NSHUTDN_3V3: length 25.4
  TOP w0.127: v1(13.84,17.14) 14.02,17.33 U2.3
  BOTTOM w0.127: 33.55,10.29 31.75,10.29 30.86,11.18 30.86,12.45 30.61,12.7 30.61,14.73 28.96,16.38 24.38,16.38 23.88,16.89 14.1,16.89 v1(13.84,17.14)
NSHUTDOWN_1V8: length 69.9
  TOP w0.127: v1(11.18,15.24) 11.05,15.11 11.05,10.03 P2.16 11.43,8.38 11.43,5.46 11.05,5.08 v1(5.71,5.08) ; R13.1 17.78,17.65 17.65,17.53 17.65,16.38 v1(18.03,16) 18.03,15.38 R28.1 ; v1(28.32,15.88) 28.83,16.38 28.83,35.81 28.17,36.47 27.05,36.47 24.23,33.66 21.82,33.66 21.48,33.32 U5.A6 21.33,33.37
  BOTTOM w0.127: v1(11.18,15.24) 13.34,15.24 14.61,16.51 17.53,16.51 v1(18.03,16) 18.67,16.64 23.62,16.64 24.13,16.13 28.07,16.13 v1(28.32,15.88) ; v1(5.71,5.08) P1.89
RF_ANT: length 2.3
  TOP w0.157: FL1.2 R30.2
SLO: length 2.4
  TOP w0.203: U5.B1 20.63,30.3
  TOP w0.305: 20.63,30.3 21.44,29.49 C30.1
SLOW_CLK_EDGE: length 61.1
  TOP w0.127: R36.1 v1(10.41,37.72) ; v1(21.64,6.25) 21.74,6.15 33.91,6.15 34.26,6.5 35.79,6.5 36.07,6.22 v1(36.32,6.22)
  LYR3_PWR w0.127: v1(10.41,37.72) 10.48,37.66 11.52,37.66 12.04,37.13 12.04,33.63 12.88,32.8 12.88,32.18 12.52,31.83 12.52,26.9 12.88,26.54 14.86,26.54 17.4,24 17.4,22.1 20.55,18.95 20.55,17.4 21.16,16.79 21.16,15.57 v1(20.7,15.11)
  BOTTOM w0.127: v1(36.32,6.22) 36.73,6.22 37.27,5.68 37.27,4.25 36.83,3.81 P1.1 ; v1(20.7,15.11) 20.7,15.01 20.64,14.95 20.64,9.97 P2.10 19.68,8.2 v1(21.64,6.25)
SLOW_CLK_EXT_1V8: length 29.2
  TOP w0.127: v1(19.18,16) 18.94,16 R14.1 ; R25.2 v1(9.4,36.7)
  LYR3_PWR w0.127: v1(9.4,36.7) 9.32,36.7 8.13,35.51 8.13,29.97 9.65,28.45 9.65,24.77 13.79,20.64 15.81,20.64 17.4,19.05 17.4,18.43 19.18,16.65 v1(19.18,16)
SLOW_CLK_EXT_3V3: length 18.2
  TOP w0.127: v1(13.84,16.51) 14.26,16.93 U2.4
  BOTTOM w0.127: RF1.5 1.65,19.18 1.52,19.05 1.52,16.38 1.91,16 10.03,16 10.29,15.75 13.08,15.75 v1(13.84,16.51)
SLOW_CLK_INT_1V8: length 1
  TOP w0.127: OSC1.3 6.23,35.66 R26.1
TX_DEBUG_1V8: length 37.7
  TOP w0.127: P1.76 10.16,4.57 10.29,4.7 11.3,4.7 11.81,5.21 11.81,7.24 13.08,8.51 13.08,10.54 P2.15 11.68,11.94 11.68,15.68 11.37,16 11.37,17.91 11.49,18.03 11.49,22.92 10.92,23.5 10.16,23.5 9.4,24.26 9.4,29.84 10.54,30.99 11.99,30.99 13.42,32.42 U5.B24 14.56,32.42
UBAL5: length 9.7
  TOP w0.157: P3.2 33.36,43.45 R30.1
VIO_HOST: length 47.6
  TOP w0.127: U2.15 15.37,18.43 15.37,17.02 15.17,16.82 U2.6 15.17,16.28 15.14,16.26 14.78,16.26 14.77,16.27 U2.5 ; U4.5 26.63,19.9 26.8,20.07 27.3,20.07 27.56,19.81 27.76,19.81 v1(27.84,19.89)
  TOP w0.254: U2.15 15.17,19.23 v1(15.24,19.3) ; v1(15.24,19.3) 15.49,19.3 15.57,19.23 U2.14 ; v1(15.24,19.3) 14.86,19.3 14.77,19.21 U2.16 ; U3.16 8.67,19.14 8.84,19.3 v1(9.14,19.3) ; v1(9.14,19.3) 9.07,19.23 U3.15 ; v1(9.14,19.3) 9.47,18.98 U3.14 ; 25.46,15.24 25.9,15.24 R18.2 26.04,14.48 27.3,13.21 P2.3 ; 25.46,15.24 C15.2 ; 25.46,15.24 25.46,16.57 25.84,16.95 U4.14 25.84,18.85 v1(26.04,19.05)
  TOP w0.381: C11.2 v1(15.24,19.3) ; C13.2 v1(9.14,19.3)
  TOP w0.508: C34.1 31.74,19.84 R1.2 v1(31.88,20.45)
  BOTTOM w0.381: 15.24,19.94 9.68,19.94 9.14,19.41 v1(9.14,19.3) ; 15.24,19.94 v1(15.24,19.3) ; 15.24,19.94 20.19,19.94 20.57,20.32 23.8,20.32 25.07,19.05 v1(26.04,19.05) 26.87,19.89 v1(27.84,19.89) 31.32,19.89 v1(31.88,20.45)
VOUT: length 3.5
  TOP w0.508: 34.99,20.25 35.05,20.32 C10.1 ; 34.99,20.25 C9.1 34.8,20.19 34.16,20.19 R5.1 ; 34.99,20.25 34.99,18.75
N29501739: length 1.5
  TOP w0.381: 36.89,18.75 36.96,18.81 C8.1
N29523209: length 23.7
  TOP w0.508: R6.1 36.84,24.77 v1(36.45,24.77) ; 8,29.34 8.27,29.6 FB2.1 ; R5.2 34.04,21.84 v1(33.27,22.61) ; FB3.1 v1(18.8,22.1) v1(19.43,22.1)
  TOP w0.762: 8,29.34 8,27.43 J1.1 8.13,26.92 8.13,24.13 v1(9.02,23.24) v1(9.65,22.61)
  BOTTOM w0.762: v1(9.02,23.24) v1(9.65,22.61) 16.51,22.61 17.02,22.1 v1(18.8,22.1) v1(19.43,22.1)
N29523238: length 1
  TOP w0.254: R8.1 6.24,30.73 FB2.2
N29550712: length 1
  TOP w0.254: FB3.2 17.01,21.11 R9.1
N29596482: length 9.7
  TOP w0.127: U5.B4 21.58,32.42 22.33,31.67 24.66,31.67 25.2,31.14 25.2,28.25 Y1.1 26.21,27.85 C22.2
N29596500: length 9.7
  TOP w0.127: U5.A4 21.42,32.12 22.23,31.32 24.43,31.32 24.84,30.91 24.84,27.2 24.34,26.7 Y1.3 24.09,26.76 C23.2
N29616633: length 1.1
  TOP w0.127: U4.7 25.84,20.63 R20.2
N29628438: length 1.3
  TOP w0.127: R12.1 14.99,15.37 15.57,15.95 U2.7
N29630665: length 1.1
  TOP w0.127: R15.1 9.47,15.56 U3.7
N29632228: length 3.6
  TOP w0.127: U4.15 26.23,17.2 26.42,17.02 26.8,17.02 ; 26.8,17.02 27.05,16.76 R19.1 R18.1 ; 26.8,17.02 26.63,17.18 U4.16
N29659196: length 37.3
  TOP w0.127: v1(6.35,37.72) R36.2 R25.1 6.24,36.7 R26.2 6.21,36.7 ; 13.86,33.32 U5.A25 13.46,33.32 12.78,32.64 v1(12.44,32.64)
  LYR3_PWR w0.127: v1(19.56,15.24) 19.63,15.32 19.63,16.84 19.48,16.99 19.48,19.38 17.02,21.84 17.02,23.95 14.81,26.16 12.69,26.16 12.22,26.64 12.22,32.41 v1(12.44,32.64)
  BOTTOM w0.127: v1(6.35,37.72) 9.14,37.72 9.91,36.96 9.91,36.07 9.65,35.81 9.65,33.91 10.41,33.15 11.93,33.15 v1(12.44,32.64)
N29662683: length 1.2
  TOP w0.127: R13.2 16.81,17.33 U2.10
N29662686: length 1.1
  TOP w0.127: R14.2 16.91,16.93 U2.9
N29662812: length 1.7
  TOP w0.127: R21.2 24.14,17.16 25.05,18.07 U4.12
N29662815: length 1.5
  TOP w0.127: U4.11 24.95,18.47 24.51,18.03 R22.2
N29662818: length 1.5
  TOP w0.127: U4.10 24.95,18.87 24.51,19.3 R23.2
N29662821: length 1.7
  TOP w0.127: U4.9 24.93,19.27 24.07,20.13 R24.2
N29665006: length 3.5
  TOP w0.127: R35.2 9.4,33.27 8.79,32.66 OSC1.1 8.3,31.78 R34.2
N295651990: length 1.5
  TOP w0.127: R4.2 33.91,11.67 33.91,11.3 33.15,10.54 D1.1

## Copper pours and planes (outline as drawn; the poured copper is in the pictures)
1V8_IN on LYR3_PWR: 35.81,4.7 35.56,4.95 35.56,7.75 37.08,9.27 37.08,23.62 37.47,24 38.61,24 38.86,23.75 38.86,8.26 37.34,6.73 37.34,4.83 37.21,4.7
GND on TOP (solid shape): 12.02,31.77 11.02,31.77 11.02,35.57 12.02,35.57
GND on TOP (solid shape): 21.57,41.32 17.77,41.32 17.77,42.32 21.57,42.32
GND on TOP (solid shape): 21.57,25.02 17.77,25.02 17.77,26.02 21.57,26.02
GND on TOP (solid shape): 28.32,31.77 27.32,31.77 27.32,35.57 28.32,35.57
GND on TOP (solid shape): 12.02,26.02 15.57,26.02 15.57,25.02 11.02,25.02 11.02,29.57 12.02,29.57
GND on TOP (solid shape): 15.57,41.32 12.02,41.32 12.02,37.77 11.02,37.77 11.02,42.32 15.57,42.32
GND on TOP (solid shape): 28.32,37.77 27.32,37.77 27.32,41.32 23.77,41.32 23.77,42.32 28.32,42.32
GND on TOP (solid shape): 28.32,25.02 23.77,25.02 23.77,26.02 27.32,26.02 27.32,29.57 28.32,29.57
GND on TOP (solid shape): 33.38,47.13 26.55,47.13 26.55,46.07 25.4,46.07 25.4,47.07 24.4,47.07 24.4,46.07 23.4,46.07 23.4,48.2 31.4,48.2 31.4,51.07 25.4,51.07 25.4,50.07 26.4,50.07 26.4,49.07 23.4,49.07 23.4,50.07 24.4,50.07 24.4,52.07 7.4,52.07 7.4,53.07 33.38,53.07
GND on TOP: 0.51,46.23 38.86,46.23 38.86,8.26 37.34,6.73 37.34,0.51 17.53,0.51 17.53,6.48 17.02,6.99 14.73,6.99 14.22,6.48 14.22,0.51 2.03,0.51 2.03,6.73 0.51,8.25 ; 50 cut-outs
GND on BOTTOM: 0.51,46.23 38.86,46.23 38.86,8.26 37.34,6.73 37.34,0.51 17.53,0.51 17.53,6.48 17.02,6.99 14.73,6.99 14.22,6.48 14.22,0.51 2.03,0.51 2.03,6.73 0.51,8.25 ; 3 cut-outs
GND on LYR2_GND: 15.57,6.99 14.73,6.99 14.22,6.48 14.22,0.51 2.03,0.51 2.03,6.73 0.51,8.26 0.51,46.23 38.86,46.23 38.86,8.26 37.34,6.73 37.34,0.51 17.53,0.51 17.53,6.48 17.02,6.99 15.62,6.99 15.62,-28.7 90.12,-28.7 90.12,-41.02 51.13,-41.02 51.13,-34.67 15.57,-34.67 ; 1 cut-out
GND on LYR3_PWR: 15.57,6.99 14.73,6.99 14.22,6.48 14.22,0.51 2.03,0.51 2.03,6.73 0.51,8.26 0.51,46.23 38.86,46.23 38.86,8.26 37.34,6.73 37.34,0.51 17.53,0.51 17.53,6.48 17.02,6.99 15.62,6.99 15.62,-28.7 90.12,-28.7 90.12,-41.02 51.13,-41.02 51.13,-34.67 15.57,-34.67 ; 1 cut-out
VDD_1V8 on LYR3_PWR: 15.37,40.51 8.38,40.51 4.19,36.32 4.19,13.97 7.11,10.29 10.16,10.29 10.79,10.92 10.79,12.45 6.73,16.51 6.73,35.69 9.4,38.35 13.59,38.35 13.97,37.97 13.97,31.62 16,29.72 17.65,29.72 18.03,30.1 18.03,30.73 17.78,30.99 16.26,30.99 15.88,31.24 15.88,36.45 16.13,36.7 16.89,37.34 16.89,38.99
ANT on TOP (solid shape): 23.66,49.14 22.72,48.29 22.72,45.95 22.57,45.95 22.57,48.36 23.54,49.24
N29523209 on LYR3_PWR: 18.41,22.1 18.41,22.48 18.67,22.73 31.37,22.73 33.91,25.27 36.45,25.27 37.72,24.38 37.72,22.23 36.96,21.46 19.05,21.46

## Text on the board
BOTTOM: 6546200 | LAYER 2 - BOTTOM SIDE | 4
Ref Des/Assembly Bottom: VIEWED FROM TOP SIDE | ASSEMBLY - BOTTOM SIDE | 2
Board Geometry/Soldermask Bottom: SOLDERMASK - SECONDARY SIDE | 4
Package Geometry/Pastemask Bottom: SOLDERPASTE - SECONDARY SIDE | 8
Ref Des/Silkscreen Bottom: SILKSCREEN - SECONDARY SIDE | 6
User.Comments: TI-ECS | 10 | CC256xQFN-EM | 6546200 | TEXAS INSTRUMENTS | 1.2 | 11/20/2012
TOP: LAYER 1 - PRIMARY SIDE | 1
Ref Des/Assembly Top: A1 | SEE BOM FOR DETAILS. | PLACE ONE ONLY, | BUT NOT BOTH. | VIEWED FROM TOP SIDE | ASSEMBLY - TOP SIDE | 1 | 2
Board Geometry/Soldermask Top: SOLDERMASK - PRIMARY SIDE | 3
Package Geometry/Pastemask Top: SOLDERPASTE - PRIMARY SIDE | 7
Ref Des/Silkscreen Top: A30 | A21 | P1 | PWR | SILKSCREEN - PRIMARY SIDE | 5
LYR2_GND: LAYER 2 - GND | 2
LYR3_PWR: LAYER 3 - GND/PWR | 3
DIMENSION: 0.031" RAD | (2 PLCS) | SHIELD DIMENSIONS | 1 | 0 | VIEWED FROM PRIMARY SIDE | FABRICATION DRAWING
User.6: 15. | 16. | 19.99 MIL TRACES ON TOP SIDE (LAYER 1) ARE TO BE 50 OHM +/-10% | THESE WILL DECOUPLE TO THE GND PLANE ON LAYER 2. | ALL VIAS WILL BE FILLED WITH NON-CONDUCTIVE EPOXY. | X
User.7: SCALE: NONE | LAYER 1 | LAYER 3 | LAYER 2 | LAYER 4 | BSLK | SMS | TSLK | SMC | LAYER SCHEDULE
User.9: FID1 | A30 | A21 | * | 1 | C18 | C19 | R28 | R13 | R14 | C35 | C20 | C32 | C28 | C29 | C24 | C30 | Y1 | C21 | R4 | D1 | C6 | C2 | C1 | C31 | C26 | C23 | C22 | OSC1 | U5 | ANT1 | P1 | P3 | CC256xQFN-EM  Rev 1.2 | TP1 | GND | C33 | R8 | U3 | VDD_1V8 | R36 | R15 | R7 | R34 | FB2 | J1 | R25 | U2 | R12 | DEBUG HDR | R27 | SHLD1 | R22 | R23 | R21 | R24 | C16 | C15 | R30 | FL1 | R18 | R20 | R19 | U4 | P2 | TP2 | R2 | FB1 | VBAT_CC | TEST PORT | R6 | C5 | J2 | 1V8 | PWR | C7 | 2 | TP3 | C10 | U1 | RF1 | 100 | R26 | C13 | R35 | C14 | C36 | C11 | C17 | C12 | C25 | FB3 | R9 | C27 | R29 | R11 | C34 | R3 | R10 | R1 | R5 | C9 | C8 | CC256xQFN-EM | REV 1.2 | RF2 | 19 | MEC6 | 20 | 99 | ALL DIMENSION ARE IN MILS | UNLESS OTHERWISE SPECIFIED | ionDesign | CRAIG BOHREN | MIIUEL SANCHEZ | SCALE  NONE | REV | 1.2 | SIZE | B | SHEET   OF | DRAWN BY: | CHECKED BY: | APPROVED BY: | Pb | ASSEMBLY TOP SIDE | ASSEMBLY BOTTOM SIDE | ASSEMBLY: | TEXAS INSTRUMENTS
User.11: FIGURE | SIZE | 8.0 | 20.0 | 38.0 | 53.0 | DRILL CHART: TOP to BOTTOM | ALL UNITS ARE IN MILS | TOLERANCE | +0.0/-8.0 | +3.0/-3.0 | +3.0/-0.0 | PLATED | NON-PLATED | QTY | 646 | 1 | 24 | 4
